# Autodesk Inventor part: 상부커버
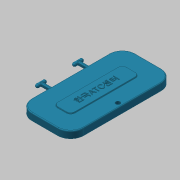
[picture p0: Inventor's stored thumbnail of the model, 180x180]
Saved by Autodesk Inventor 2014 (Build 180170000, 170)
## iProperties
Created: 2016-02
Part Number: 상부커버
Material: ABS 플라스틱
Document SubType Name: Modeling
Designer: mduedu
Density: 2.71 g/cm^3
Mass: 42.0587 g
Surface Area: 149.263 cm^2
Volume: 15.5198 cm^3
Appearance: 터키옥색
Author: mduedu
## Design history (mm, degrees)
sketch "스케치1"
  geometry: L1 (30, 60)-(-30, 60); L2 (-30, 60)-(-30, -60); L3 (-30, -60)-(30, -60); L4 (30, -60)-(30, 60); L5 (30, 60)-(-30, -60); L6 (-30, 60)-(30, -60); 1 further point
  constraints: 12 end point, 2 midpoint, 2 parallel, 1 horizontal, 1 perpendicular
  dimensions: "d0" = 60 distance of L2.end L3.end; "d2" = 120 distance of L1.end L2.end
extrude "돌출1" new body sketch "스케치1" distance "d3" = 8; taper "d4" = 0 deg
fillet "모깎기1" dims "d5" = 15
node "작업 평면1"
sketch "스케치7"
  geometry: L1 (-39, 4)-(129, 4) reference; L2 (65, 2)-(68, 2); L3 (68, 2)-(68, 6); L4 (68, 6)-(65, 6); L5 (65, 6)-(65, 2); L6 (65, 2)-(68, 6); L7 (68, 2)-(65, 6); 2 further points
  constraints: 12 end point, 2 midpoint, 2 parallel, 1 horizontal, 1 perpendicular, 1 point on line
  dimensions: "d33" = 4 distance of L2.end L3.end; "d35" = 3 distance of L3.end L4.end; "d36" = 20 distance from line of L5 point (45, 0)
extrude "돌출3" join sketch "스케치7" distance "d37" = 15; taper "d38" = 0 deg
fillet "모깎기6" dims "d39" = 2
node "작업 평면3"
sketch "스케치8"
  geometry: A1 r 2 centre (-13, 2) between (-13, 4) and (-13, 0) reference; 2 further points
  constraints: 1 coincident, 1 vertical alignment, 2 other
extrude "돌출4" join sketch "스케치8" stored distance "d40" = 12; taper "d41" = 0 deg
fillet "모깎기7" dims "d42" = 2
fillet "모깎기8" dims "d43" = 1
fillet "모깎기9" dims "d44" = 1
sketch "스케치2"
  geometry: L1 (30, 45)-(30, -45) reference; L2 (15, -60)-(-15, -60) reference; L3 (-30, -45)-(-30, 45) reference; L4 (-15, 60)-(15, 60) reference; L5 (25, 45)-(25, -45); L6 (15, -55)-(-15, -55); L7 (-25, -45)-(-25, 45); L8 (-15, 55)-(15, 55); A1 r 15 centre (15, 45) between (30, 45) and (15, 60) reference; A2 r 15 centre (15, -45) between (15, -60) and (30, -45) reference; A3 r 15 centre (-15, -45) between (-30, -45) and (-15, -60) reference; A4 r 15 centre (-15, 45) between (-15, 60) and (-30, 45) reference; A5 r 10 centre (15, 45) between (25, 45) and (15, 55); A6 r 10 centre (15, -45) between (15, -55) and (25, -45); A7 r 10 centre (-15, -45) between (-25, -45) and (-15, -55); A8 r 10 centre (-15, 45) between (-15, 55) and (-25, 45); 4 further points
  constraints: 8 end point, 8 point on circle, 4 centre point, 4 midpoint, 7 other
  dimensions: "d8" = 5 distance between parallel lines of L7 L3
hole "구멍1" sketch "스케치2" at (25, 0) diameter "d9" = 5; stored, may be unused: countersink angle "d13" = 90 deg, drill point angle "d15" = 118 deg; dims "d10" = 6, "d11" = 4, "d12" = 2, "d14" = 8
sketch "스케치3"
  geometry: L1 (10, -40)-(-10, -40); L2 (-10, -40)-(-10, 40); L3 (-10, 40)-(10, 40); L4 (10, 40)-(10, -40); L5 (10, -40)-(-10, 40); L6 (-10, -40)-(10, 40); 1 further point
  constraints: 12 end point, 2 midpoint, 2 parallel, 1 horizontal, 1 perpendicular
  dimensions: "d16" = 80 distance of L1.end L2.end; "d18" = 20 distance of L2.end L3.end
extrude "돌출2" join sketch "스케치3" distance "d19" = 1; taper "d20" = 0 deg
fillet "모깎기2" dims "d21" = 5
fillet "모깎기3" dims "d22" = 0.3
sketch "스케치4"
  geometry: 2 further points
  constraints: 1 coincident, 1 other
feature "엠보싱1" sketch "스케치4" dims "d8" = 5, "d24" = 0.5, "d25" = 0
fillet "모깎기10" dims "d45" = 1
node "솔리드1"
mirror "대칭1"
node "절단 모서리 투영1"
